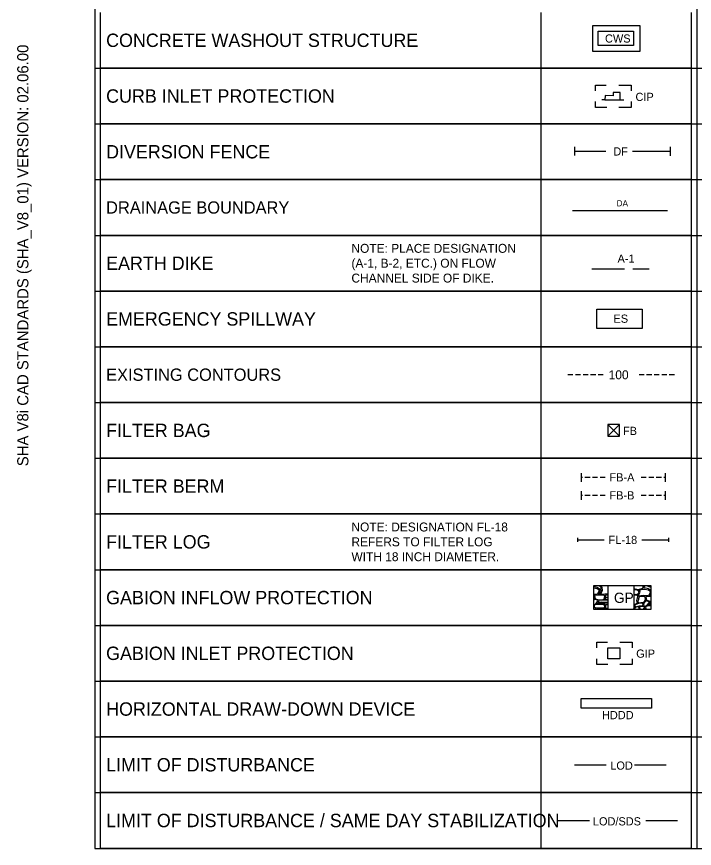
# Model space of a CAD drawing. Extents: x 1.3 to 34, y 0 to 22.5.
# Drawn here: x 1.3 to 7.38, y 7.83 to 15.29 of the extents above; entities that cross this region are included whole.
import ezdxf

# ---------------------------------------------------------------- set-up
doc = ezdxf.new("R2010")
doc.units = 0
for name, color, linetype in [('ANNO-SYMB', 7, 'Continuous'), ('ANNO-TABL', 7, 'Continuous'), ('USER-LINE', 7, 'Continuous'), ('USER-TEXT', 7, 'Continuous')]:
    doc.layers.add(name, color=color, linetype=linetype)

msp = doc.modelspace()

# ---------------------------------------------------------------- linework, layer by layer
at = {"layer": 'ANNO-SYMB'}
for p, q in [((6.5736, 14.5417), (6.5464, 14.5417)), ((6.7074, 14.5417), (6.7417, 14.5417)), ((6.3033, 14.08), (6.3033, 14.1192)), ((7.1596, 14.0789), (7.1596, 14.1181)), ((6.3033, 14.08), (6.5815, 14.08)), ((6.3033, 14.0407), (6.3033, 14.08)), ((6.82, 14.0789), (7.1596, 14.0789)), ((7.1596, 14.0397), (7.1596, 14.0789)), ((6.283, 13.5477), (7.1353, 13.5477)), ((6.4562, 13.025), (6.6031, 13.025)), ((6.6031, 13.025), (6.75, 13.025)), ((6.2866, 12.075), (6.2409, 12.075)), ((6.3544, 12.075), (6.3087, 12.075)), ((6.4222, 12.075), (6.3765, 12.075)), ((6.4901, 12.075), (6.4443, 12.075)), ((6.5579, 12.075), (6.5122, 12.075)), ((6.925, 12.075), (6.8793, 12.075)), ((6.9929, 12.075), (6.9471, 12.075)), ((7.0607, 12.075), (7.0149, 12.075)), ((7.1285, 12.075), (7.0828, 12.075)), ((7.1963, 12.075), (7.1506, 12.075)), ((6.6, 11.5228), (6.7044, 11.6272)), ((6.6, 11.6272), (6.7044, 11.5228)), ((6.3619, 11.1512), (6.3619, 11.1898)), ((6.3619, 11.1126), (6.3619, 11.1512)), ((6.3719, 11.1512), (6.3625, 11.1512)), ((6.4397, 11.1512), (6.394, 11.1512)), ((6.5075, 11.1512), (6.4618, 11.1512)), ((6.5753, 11.1512), (6.5296, 11.1512)), ((6.9441, 11.1512), (6.8983, 11.1512)), ((7.0119, 11.1512), (6.9662, 11.1512)), ((7.0797, 11.1512), (7.034, 11.1512)), ((7.1168, 11.1512), (7.1018, 11.1512)), ((7.1168, 11.1512), (7.1168, 11.1898)), ((7.1168, 11.1126), (7.1168, 11.1512)), ((6.3619, 10.9897), (6.3619, 11.0283)), ((6.3619, 10.9511), (6.3619, 10.9897)), ((6.3719, 10.9897), (6.3625, 10.9897)), ((6.4397, 10.9897), (6.394, 10.9897)), ((6.5075, 10.9897), (6.4618, 10.9897)), ((6.5753, 10.9897), (6.5296, 10.9897)), ((6.9441, 10.9897), (6.8983, 10.9897)), ((7.0119, 10.9897), (6.9662, 10.9897)), ((7.0797, 10.9897), (7.034, 10.9897)), ((7.1168, 10.9897), (7.1018, 10.9897)), ((7.1168, 10.9897), (7.1168, 11.0283)), ((7.1168, 10.9511), (7.1168, 10.9897)), ((6.3265, 10.6125), (6.3265, 10.5747)), ((7.1439, 10.6125), (7.1439, 10.5747)), ((6.3265, 10.5936), (6.5658, 10.5936)), ((6.9026, 10.5936), (7.1439, 10.5936)), ((6.5993, 10.1829), (6.5993, 9.9671)), ((6.8311, 10.1829), (6.8311, 9.9671)), ((6.3, 8.575), (6.5855, 8.575)), ((6.8387, 8.575), (7.1229, 8.575)), ((6.15, 8.075), (6.4355, 8.075)), ((6.9387, 8.075), (7.2229, 8.075))]:
    msp.add_line(p, q, dxfattribs=at)
for points in [[(6.464, 15.2081), (6.886, 15.2081), (6.886, 14.9753), (6.464, 14.9753)], [(6.5117, 15.1574), (6.8281, 15.1574), (6.8281, 15.0278), (6.5117, 15.0278)], [(6.5, 12.6613), (6.9083, 12.6613), (6.9083, 12.4887), (6.5, 12.4887)], [(6.6, 11.5228), (6.7044, 11.5228), (6.7044, 11.6272), (6.6, 11.6272)], [(6.475, 10.1829), (6.9854, 10.1829), (6.9854, 9.9671), (6.475, 9.9671)], [(6.8751, 10.0883), (6.8731, 10.097), (6.8896, 10.1222), (6.8817, 10.1403), (6.9061, 10.1494), (6.9297, 10.1519), (6.9649, 10.1432), (6.9798, 10.1329), (6.9785, 10.1176), (6.9628, 10.0908), (6.9173, 10.0929)], [(6.4809, 10.0935), (6.4844, 10.0646), (6.5173, 10.055), (6.5497, 10.0559), (6.5664, 10.0607), (6.5694, 10.0778), (6.5708, 10.0874), (6.5651, 10.0939), (6.5444, 10.0961), (6.5085, 10.0966)], [(6.5153, 10.1049), (6.5273, 10.1317), (6.5281, 10.1457), (6.5406, 10.1437), (6.543, 10.1379), (6.5277, 10.1053)], [(6.8706, 10.0269), (6.8951, 10.0313), (6.9223, 10.0321), (6.9364, 10.0544), (6.9346, 10.0803), (6.914, 10.0838), (6.8794, 10.0803), (6.8732, 10.0649), (6.8732, 10.0536), (6.8684, 10.0431)], [(6.4756, 9.9898), (6.5045, 9.9841), (6.5392, 9.9833), (6.5681, 9.9846), (6.5708, 9.9955), (6.5699, 10.0064), (6.5585, 10.0113), (6.5282, 10.0139), (6.4931, 10.0121), (6.4813, 10.0091), (6.4752, 9.9973)], [(6.8438, 9.9919), (6.8789, 10.0024), (6.9122, 10.0046), (6.9157, 10.0155), (6.9109, 10.0247), (6.8837, 10.0247), (6.8403, 10.0085)], [(6.9197, 10.0028), (6.9342, 9.9971), (6.9539, 10.0098), (6.9675, 10.0264), (6.9706, 10.0369), (6.9421, 10.0466), (6.932, 10.0339), (6.921, 10.0238)], [(6.6, 9.6236), (6.7071, 9.6236), (6.7071, 9.5264), (6.6, 9.5264)], [(6.9904, 9.0831), (6.3596, 9.0831), (6.3596, 9.1707), (6.9904, 9.1707)]]:
    msp.add_lwpolyline(points, close=True, dxfattribs=at)
for points in [[(6.49, 14.6219), (6.49, 14.6728), (6.5852, 14.6728)], [(6.6969, 14.6728), (6.8086, 14.6728), (6.8086, 14.6219)], [(6.5736, 14.5417), (6.711, 14.5417), (6.7092, 14.6067), (6.6477, 14.6067), (6.6477, 14.5778), (6.5754, 14.5796), (6.5736, 14.5417)], [(6.5898, 14.4731), (6.49, 14.4731), (6.49, 14.5247)], [(6.8086, 14.5247), (6.8086, 14.4731), (6.6969, 14.4731)], [(6.8234, 13.025), (6.9703, 13.025)], [(6.5205, 10.1829), (6.5343, 10.175), (6.5422, 10.1532), (6.5294, 10.1519), (6.5042, 10.166), (6.475, 10.172)], [(6.475, 10.1638), (6.5046, 10.1565), (6.5195, 10.1461), (6.5182, 10.1309), (6.5025, 10.1041), (6.475, 10.1053)], [(6.5718, 10.1047), (6.5546, 10.1028), (6.5356, 10.1049), (6.5509, 10.1412), (6.5488, 10.1635), (6.5404, 10.1829)], [(6.8311, 10.1528), (6.8445, 10.1544), (6.8743, 10.1473), (6.9144, 10.1597), (6.9202, 10.1791), (6.9176, 10.1829)], [(6.8341, 10.1829), (6.8321, 10.1762), (6.8311, 10.1751)], [(6.9854, 10.1411), (6.9645, 10.1527), (6.9243, 10.161), (6.9289, 10.1775), (6.9425, 10.182), (6.9765, 10.1721), (6.9854, 10.167)], [(6.9662, 10.1829), (6.9854, 10.1769)], [(6.475, 10.066), (6.476, 10.0677), (6.4743, 10.0935)], [(6.5993, 10.107), (6.5735, 10.1047)], [(6.5993, 10.096), (6.5856, 10.0954), (6.576, 10.0901), (6.575, 10.0796), (6.5993, 10.0777)], [(6.8311, 10.1036), (6.8499, 10.1069), (6.8644, 10.1007), (6.8809, 10.1213), (6.8743, 10.1366), (6.8569, 10.1445), (6.8311, 10.1438)], [(6.8311, 10.0971), (6.8499, 10.0999), (6.8644, 10.0933), (6.8688, 10.085)], [(6.8311, 10.0175), (6.8416, 10.016), (6.8638, 10.0241), (6.8604, 10.0452), (6.8688, 10.0835)], [(6.9854, 10.0831), (6.9688, 10.0833), (6.9412, 10.0803), (6.9447, 10.0514), (6.9776, 10.0418), (6.9854, 10.042)], [(6.9854, 10.092), (6.9756, 10.0916), (6.9854, 10.1135)], [(6.4738, 10.0104), (6.4936, 10.0231), (6.5072, 10.0397), (6.5102, 10.0502), (6.4817, 10.0598), (6.475, 10.0513)], [(6.5714, 10.0165), (6.5335, 10.0191), (6.498, 10.0178), (6.5076, 10.0288), (6.5304, 10.0318), (6.5501, 10.0309), (6.5718, 10.0295)], [(6.5714, 10.0523), (6.5484, 10.0506), (6.5195, 10.0498), (6.5142, 10.0432), (6.512, 10.0353), (6.5458, 10.0371), (6.5714, 10.0344)], [(6.5993, 10.051), (6.5735, 10.0522)], [(6.5735, 10.0344), (6.5952, 10.0326), (6.5993, 10.0314)], [(6.5735, 10.0165), (6.5952, 10.0182), (6.5993, 10.019)], [(6.5993, 10.0257), (6.5943, 10.0273), (6.5736, 10.0294)], [(6.5993, 10.0718), (6.5779, 10.0729), (6.575, 10.0695), (6.575, 10.0599), (6.5993, 10.0578)], [(6.5993, 10.0115), (6.5972, 10.011), (6.577, 10.0076), (6.5784, 9.9831), (6.5993, 9.9801)], [(6.8311, 9.975), (6.8335, 9.9747), (6.8383, 9.9915), (6.8344, 10.0083), (6.8311, 10.0091)], [(6.9854, 10.0005), (6.9535, 9.9989), (6.9416, 9.9958), (6.9355, 9.984), (6.9359, 9.9766), (6.9649, 9.9709), (6.9854, 9.9704)], [(6.9854, 10.0056), (6.9583, 10.0046), (6.9679, 10.0155), (6.9854, 10.0179)], [(6.9854, 10.0367), (6.9798, 10.0365), (6.9745, 10.0299), (6.9723, 10.0221), (6.9854, 10.0227)], [(6.4975, 9.9671), (6.4958, 9.9784), (6.4769, 9.9846), (6.475, 9.9844)], [(6.5718, 9.9765), (6.5458, 9.9776), (6.5054, 9.978), (6.5059, 9.9671)], [(6.5993, 9.9728), (6.5736, 9.9765)], [(6.8826, 9.9671), (6.8796, 9.9829), (6.8724, 9.9929), (6.844, 9.9853), (6.8392, 9.9665)], [(6.9167, 9.9671), (6.9289, 9.9827), (6.9285, 9.9914), (6.9083, 9.9963), (6.8811, 9.9954), (6.8872, 9.9801), (6.8889, 9.9671)], [(6.9501, 9.9671), (6.9372, 9.9713), (6.9271, 9.9704), (6.9241, 9.9671)], [(6.5002, 9.6236), (6.5002, 9.6745), (6.5954, 9.6745)], [(6.7071, 9.6745), (6.8188, 9.6745), (6.8188, 9.6236)], [(6.6, 9.4749), (6.5002, 9.4749), (6.5002, 9.5264)], [(6.8188, 9.5264), (6.8188, 9.4749), (6.7071, 9.4749)]]:
    msp.add_lwpolyline(points, dxfattribs=at)
at = {"layer": 'ANNO-TABL'}
for p, q in [((2, 14.825), (18.2, 14.825)), ((2, 14.325), (18.2, 14.325)), ((2, 13.825), (18.2, 13.825)), ((2, 13.325), (18.2, 13.325)), ((2, 12.825), (18.2, 12.825)), ((2, 12.325), (18.2, 12.325)), ((2, 11.825), (18.2, 11.825)), ((2, 11.325), (18.2, 11.325)), ((2, 10.825), (18.2, 10.825)), ((2, 10.325), (18.2, 10.325)), ((2, 9.825), (18.2, 9.825)), ((2, 9.325), (18.2, 9.325)), ((2, 8.825), (18.2, 8.825)), ((2, 8.325), (18.2, 8.325)), ((2, 7.825), (18.2, 7.825))]:
    msp.add_line(p, q, dxfattribs=at)
msp.add_lwpolyline([(2, 7.825), (7.4, 7.825), (7.4, 19.825), (2, 19.825)], close=True, dxfattribs=at)
at = {"layer": 'USER-LINE'}
for p, q in [((2.05, 14.825), (2.05, 15.325)), ((6, 14.825), (6, 15.325)), ((7.35, 14.825), (7.35, 15.325)), ((2.05, 14.325), (2.05, 14.825)), ((6, 14.825), (2.05, 14.825)), ((7.35, 14.825), (6, 14.825)), ((6, 14.325), (6, 14.825)), ((7.35, 14.325), (7.35, 14.825)), ((2.05, 13.825), (2.05, 14.325)), ((6, 14.325), (2.05, 14.325)), ((7.35, 14.325), (6, 14.325)), ((6, 13.825), (6, 14.325)), ((7.35, 13.825), (7.35, 14.325)), ((2.05, 13.325), (2.05, 13.825)), ((6, 13.825), (2.05, 13.825)), ((7.35, 13.825), (6, 13.825)), ((6, 13.325), (6, 13.825)), ((7.35, 13.325), (7.35, 13.825)), ((2.05, 12.825), (2.05, 13.325)), ((6, 13.325), (2.05, 13.325)), ((7.35, 13.325), (6, 13.325)), ((6, 12.825), (6, 13.325)), ((7.35, 12.825), (7.35, 13.325)), ((2.05, 12.325), (2.05, 12.825)), ((6, 12.825), (2.05, 12.825)), ((7.35, 12.825), (6, 12.825)), ((6, 12.325), (6, 12.825)), ((7.35, 12.325), (7.35, 12.825)), ((2.05, 11.825), (2.05, 12.325)), ((6, 12.325), (2.05, 12.325)), ((7.35, 12.325), (6, 12.325)), ((6, 11.825), (6, 12.325)), ((7.35, 11.825), (7.35, 12.325)), ((2.05, 11.325), (2.05, 11.825)), ((6, 11.825), (2.05, 11.825)), ((7.35, 11.825), (6, 11.825)), ((6, 11.325), (6, 11.825)), ((7.35, 11.325), (7.35, 11.825)), ((6, 11.325), (2.05, 11.325)), ((2.05, 10.825), (2.05, 11.325)), ((7.35, 11.325), (6, 11.325)), ((6, 10.825), (6, 11.325)), ((7.35, 10.825), (7.35, 11.325)), ((2.05, 10.325), (2.05, 10.825)), ((6, 10.825), (2.05, 10.825)), ((6, 10.325), (6, 10.825)), ((7.35, 10.825), (6, 10.825)), ((7.35, 10.325), (7.35, 10.825)), ((2.05, 9.825), (2.05, 10.325)), ((6, 10.325), (2.05, 10.325)), ((7.35, 10.325), (6, 10.325)), ((6, 9.825), (6, 10.325)), ((7.35, 9.825), (7.35, 10.325)), ((2.05, 9.325), (2.05, 9.825)), ((6, 9.825), (2.05, 9.825)), ((7.35, 9.825), (6, 9.825)), ((6, 9.325), (6, 9.825)), ((7.35, 9.325), (7.35, 9.825)), ((2.05, 8.825), (2.05, 9.325)), ((6, 9.325), (2.05, 9.325)), ((7.35, 9.325), (6, 9.325)), ((6, 8.825), (6, 9.325)), ((7.35, 8.825), (7.35, 9.325)), ((2.05, 8.325), (2.05, 8.825)), ((6, 8.825), (2.05, 8.825)), ((7.35, 8.825), (6, 8.825)), ((6, 8.325), (6, 8.825)), ((7.35, 8.325), (7.35, 8.825)), ((6, 8.325), (2.05, 8.325)), ((2.05, 7.825), (2.05, 8.325)), ((6, 8.325), (2.05, 8.325)), ((7.35, 8.325), (6, 8.325)), ((7.35, 8.325), (6, 8.325)), ((6, 7.825), (6, 8.325)), ((7.35, 7.825), (7.35, 8.325)), ((6, 7.825), (2.05, 7.825)), ((7.35, 7.825), (6, 7.825))]:
    msp.add_line(p, q, dxfattribs=at)

# ---------------------------------------------------------------- texts
at = {"layer": 'ANNO-SYMB'}
for s, height, p in [('CWS', 0.07344, (6.574, 15.0544)), ('CIP', 0.07344, (6.8473, 14.5305)), ('DF', 0.07344, (6.6483, 14.0412)), ('DA', 0.05508, (6.6778, 13.5852)), ('A-1', 0.07344, (6.6862, 13.0794)), ('ES', 0.07344, (6.6499, 12.5407)), ('100', 0.08035, (6.6063, 12.0335)), ('FB', 0.07344, (6.7351, 11.5338)), ('FB-A', 0.07344, (6.6141, 11.1171)), ('FB-B', 0.07344, (6.6141, 10.9555)), ('FL-18', 0.07344, (6.6058, 10.5556)), ('GP', 0.0918, (6.654, 10.0273)), ('GIP', 0.07344, (6.8534, 9.5353)), ('HDDD', 0.07344, (6.5465, 8.9838)), ('LOD', 0.07344, (6.6212, 8.5308)), ('LOD/SDS', 0.07344, (6.4652, 8.0308))]:
    msp.add_text(s, height=height, dxfattribs=at).set_placement(p)
at = {"layer": 'ANNO-TABL'}
for s, height, p in [('CONCRETE WASHOUT STRUCTURE', 0.12, (2.1, 15.015)), ('CURB INLET PROTECTION ', 0.12, (2.1, 14.515)), ('DIVERSION FENCE', 0.12, (2.1, 14.015)), ('DRAINAGE BOUNDARY', 0.11, (2.1, 13.52)), ('NOTE: PLACE DESIGNATION', 0.08, (4.3, 13.1683)), ('EARTH DIKE', 0.12, (2.1, 13.015)), ('(A-1, B-2, ETC.) ON FLOW', 0.08, (4.3, 13.035)), ('CHANNEL SIDE OF DIKE.', 0.08, (4.3, 12.9017)), ('EMERGENCY SPILLWAY', 0.12, (2.1, 12.515)), ('EXISTING CONTOURS', 0.11, (2.1, 12.02)), ('FILTER BAG', 0.12, (2.1, 11.515)), ('FILTER BERM', 0.12, (2.1, 11.015)), ('NOTE: DESIGNATION FL-18', 0.08, (4.3, 10.6683)), ('FILTER LOG', 0.12, (2.1, 10.515)), ('REFERS TO FILTER LOG', 0.08, (4.3, 10.535)), ('WITH 18 INCH DIAMETER.', 0.08, (4.3, 10.4017)), ('GABION INFLOW PROTECTION', 0.12, (2.1, 10.015)), ('GABION INLET PROTECTION', 0.12, (2.1, 9.515)), ('HORIZONTAL DRAW-DOWN DEVICE', 0.12, (2.1, 9.015)), ('LIMIT OF DISTURBANCE', 0.12, (2.1, 8.515)), ('LIMIT OF DISTURBANCE / SAME DAY STABILIZATION', 0.12, (2.1, 8.015))]:
    msp.add_text(s, height=height, dxfattribs=at).set_placement(p)
at = {"layer": 'USER-TEXT'}
msp.add_text('SHA V8i CAD STANDARDS (SHA_V8_01) VERSION: 02.06.00 ', height=0.1, rotation=90, dxfattribs=at).set_placement((1.403, 11.2535))

doc.saveas('drawing.dxf')
